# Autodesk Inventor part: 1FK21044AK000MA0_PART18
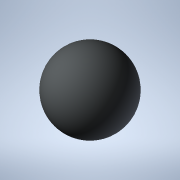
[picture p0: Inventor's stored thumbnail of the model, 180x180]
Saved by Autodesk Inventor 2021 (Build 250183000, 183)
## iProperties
Created: 2025-04
Part Number: 1FK21044AK000MA0_PART18
Material: Generic
Catalog Web Link: www.3dfindit.com
Description: -Servo synchronous motor
Document SubType Name: Modeling
Designer: psAdmin
Mass: 0.137258 g
Surface Area: 1.2868 cm^2
Volume: 0.137258 cm^3
Density: 1 g/cm^3
Appearance: PSOLRGB-212-217-219
Category: PARTsolutions
Title: 1FK21044AK000MA0_PART18
Author: Cadenas PARTsolutions
Comments: Servo synchronous motor
Sending System: PARTsolutions
Preprocessor: ST-DEVELOPER v19.3
PSOL_IDENT_0: {$CADENAS_DATA/23d-libs/siemens_ag/_cat_/87/f4/1fk21044ak000ma0.prj},216 {VTYP=3D},{NB=1FK21044AK000
PSOL_IDENT_1: MA0_PART18},{LINA=1FK21044AK000MA0_PART18},{NN=1FK21044AK000MA0_PART18},{NOPRJ=TRUE},{DATE=19.08.202
PSOL_IDENT_2: 5 14:00:48},{GEOMDATE=30.07.2025 02:00:50},{VERSION=},{LINEID=10},{WBVAR=},{WBNUMERIC=}  {NB=1FK2104
PSOL_IDENT_3: 4AK000MA0_PART18},{LINA=1FK21044AK000MA0_PART18},{KT=DUMMY},{PREVIEW=../../../_pool_/cb/72/p_d211_xx
PSOL_IDENT_4: _00434j.png},{DESCSHORT=SIMOTICS S-1FK2 HD, SINAMICS S210 3AC 400V-480V, 0.95 Nm, 6000 rpm},{DESCLON
PSOL_IDENT_5: G=SIMOTICS S-1FK2 HD servo motor M0=1.27 Nm; PN = 0.6 kW at nN=6000 rpm (380-480 V); PN = 0.4 kW at
PSOL_IDENT_6: nN=3000 rpm (200-240 V); degree of protection IP64; cylindrical shaft D19x40mm; absolute encoder 22-
PSOL_IDENT_7: bit + 12-bit multiturn (encoder AM22DQC); with OCC interface; plug size M17, rotatable; SIMOTICS S-1
PSOL_IDENT_8: FK2 servomotorfor a wide range of uses in industrial environments. SIMOTICS S‑1FK2 servomotors are c
PSOL_IDENT_9: ompact synchronous motors with a high dynamic performance that set themselves apart as a result of t
PSOL_IDENT_10: heir high power density, degree of protection and overload capability. The motors are available in t
PSOL_IDENT_11: wo variants: as High Dynamic variant (highest dynamic performance as a result of the low intrinsic m
PSOL_IDENT_12: oment of inertia for applications demanding a high dynamic performance with low moved masses) - and
PSOL_IDENT_13: as Compact variant (precise and stable closed-loop control for medium up to large moved masses as a
PSOL_IDENT_14: result of a medium intrinsic moment of inertia). SIMOTICSS‑1FK2 servomotors fully exploit their stre
PSOL_IDENT_15: ngths in a system with the SINAMICSS210 frequency converter and simple connection using the one cabl
PSOL_IDENT_16: e connection (OCC). Advantages include the short control and positioning times, fast and precise cor
PSOL_IDENT_17: rection of disturbing quantities as well as stable control with a high dynamic performance. The serv
PSOL_IDENT_18: o motors can be configured to address a wide range of requirements. For example with and without hol
PSOL_IDENT_19: ding brake, IP64 or IP65 degree of protection, singleturn or multiturn absolute encoders - to name j
PSOL_IDENT_20: ust a few. Further, the servomotors are available in different shaft heights extending from 20 to 10
PSOL_IDENT_21: 0. A shaft sealing ring is available to achieve an IP65 degree of protection and for subsequent moun
PSOL_IDENT_22: ting at the motor or as spare part. SIMOTICS - the optimum motor for each and every motion control a
PSOL_IDENT_23: pplication.},{INTNO=195125056312},{SUPPLIERALTNO=1FK2104-4AK00-0MA0},{MANUID=1FK21044AK000MA0},{MANU
PSOL_IDENT_24: NAME=Siemens},{MANUTYPEDESC=Synchronous motor 1FK2-HD 1,27 Nm},{AAU732=SIMOTICS},{AAO057=S-1FK2},{AA
PSOL_IDENT_25: U734=SIMOTICS S-1FK2 HD servo motor M0=1.27 Nm; PN = 0.6 kW at nN=6000 rpm (380-480 V); PN = 0.4 kW
PSOL_IDENT_26: at nN=3000 rpm (200-240 V); degree of protection IP64; cylindrical shaft D19x40mm; absolute encoder
PSOL_IDENT_27: 22-bit + 12-bit multiturn (encoder AM22DQC); with OCC interface; plug size M17, rotatable;},{AAW338=
PSOL_IDENT_28: Synchronous motor 1FK2-HD 1,27 Nm},{AAO742=SIMOTICS},{AAO663=4042948690994},{NOCUPEROU=1},{PRICEQUAN
PSOL_IDENT_29: TITY=1},{QUANTITYMIN=1},{QUANTITYINT=1},{CTN=85015100},{COO=DE},{AAO676=1FK2104-4AK00-0MA0},{AAO677=
PSOL_IDENT_30: Siemens AG},{ORDERUNIT=C62},{CONTENTUNIT=C62}
NB: 1FK21044AK000MA0_PART18
NT: Servo synchronous motor
NBSYN: $MANUID._PART18
LINA: 1FK21044AK000MA0_PART18
CATALOG: SIEMENS
PREVIEW: ../../../_pool_/cb/72/p_d211_xx_00434j.png
DESCSHORT: SIMOTICS S-1FK2 HD, SINAMICS S210 3AC 400V-480V, 0.95 Nm, 6000 rpm
DESCLONG: SIMOTICS S-1FK2 HD servo motor M0=1.27 Nm; PN = 0.6 kW at nN=6000 rpm (380-480 V); PN = 0.4 kW at nN=3000 rpm (200-240 V); degree of protection IP64; cylindrica
INTNO: 195125056312
SUPPLIERALTNO: 1FK2104-4AK00-0MA0
MANUID: 1FK21044AK000MA0
MANUNAME: Siemens
MANUTYPEDESC: Synchronous motor 1FK2-HD 1,27 Nm
AAU732: SIMOTICS
AAO057: S-1FK2
AAU734: SIMOTICS S-1FK2 HD servo motor M0=1.27 Nm; PN = 0.6 kW at nN=6000 rpm (380-480 V); PN = 0.4 kW at nN=3000 rpm (200-240 V); degree of protection IP64; cylindrica
AAW338: Synchronous motor 1FK2-HD 1,27 Nm
AAO742: SIMOTICS
AAO663: 4042948690994.0
NOCUPEROU: 1
PRICEQUANTITY: 1
QUANTITYMIN: 1
QUANTITYINT: 1
CTN: 85015100
COO: DE
ARTICLENO: 1FK21044AK000MA0_PART18
BOMINFO: 1FK21044AK000MA0_PART18
CREATOR: CADENAS GmbH
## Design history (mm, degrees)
feature "2025_04_17_15_37_40_0588"
body "Solid1"
